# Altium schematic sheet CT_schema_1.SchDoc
size 493 x 314 mm
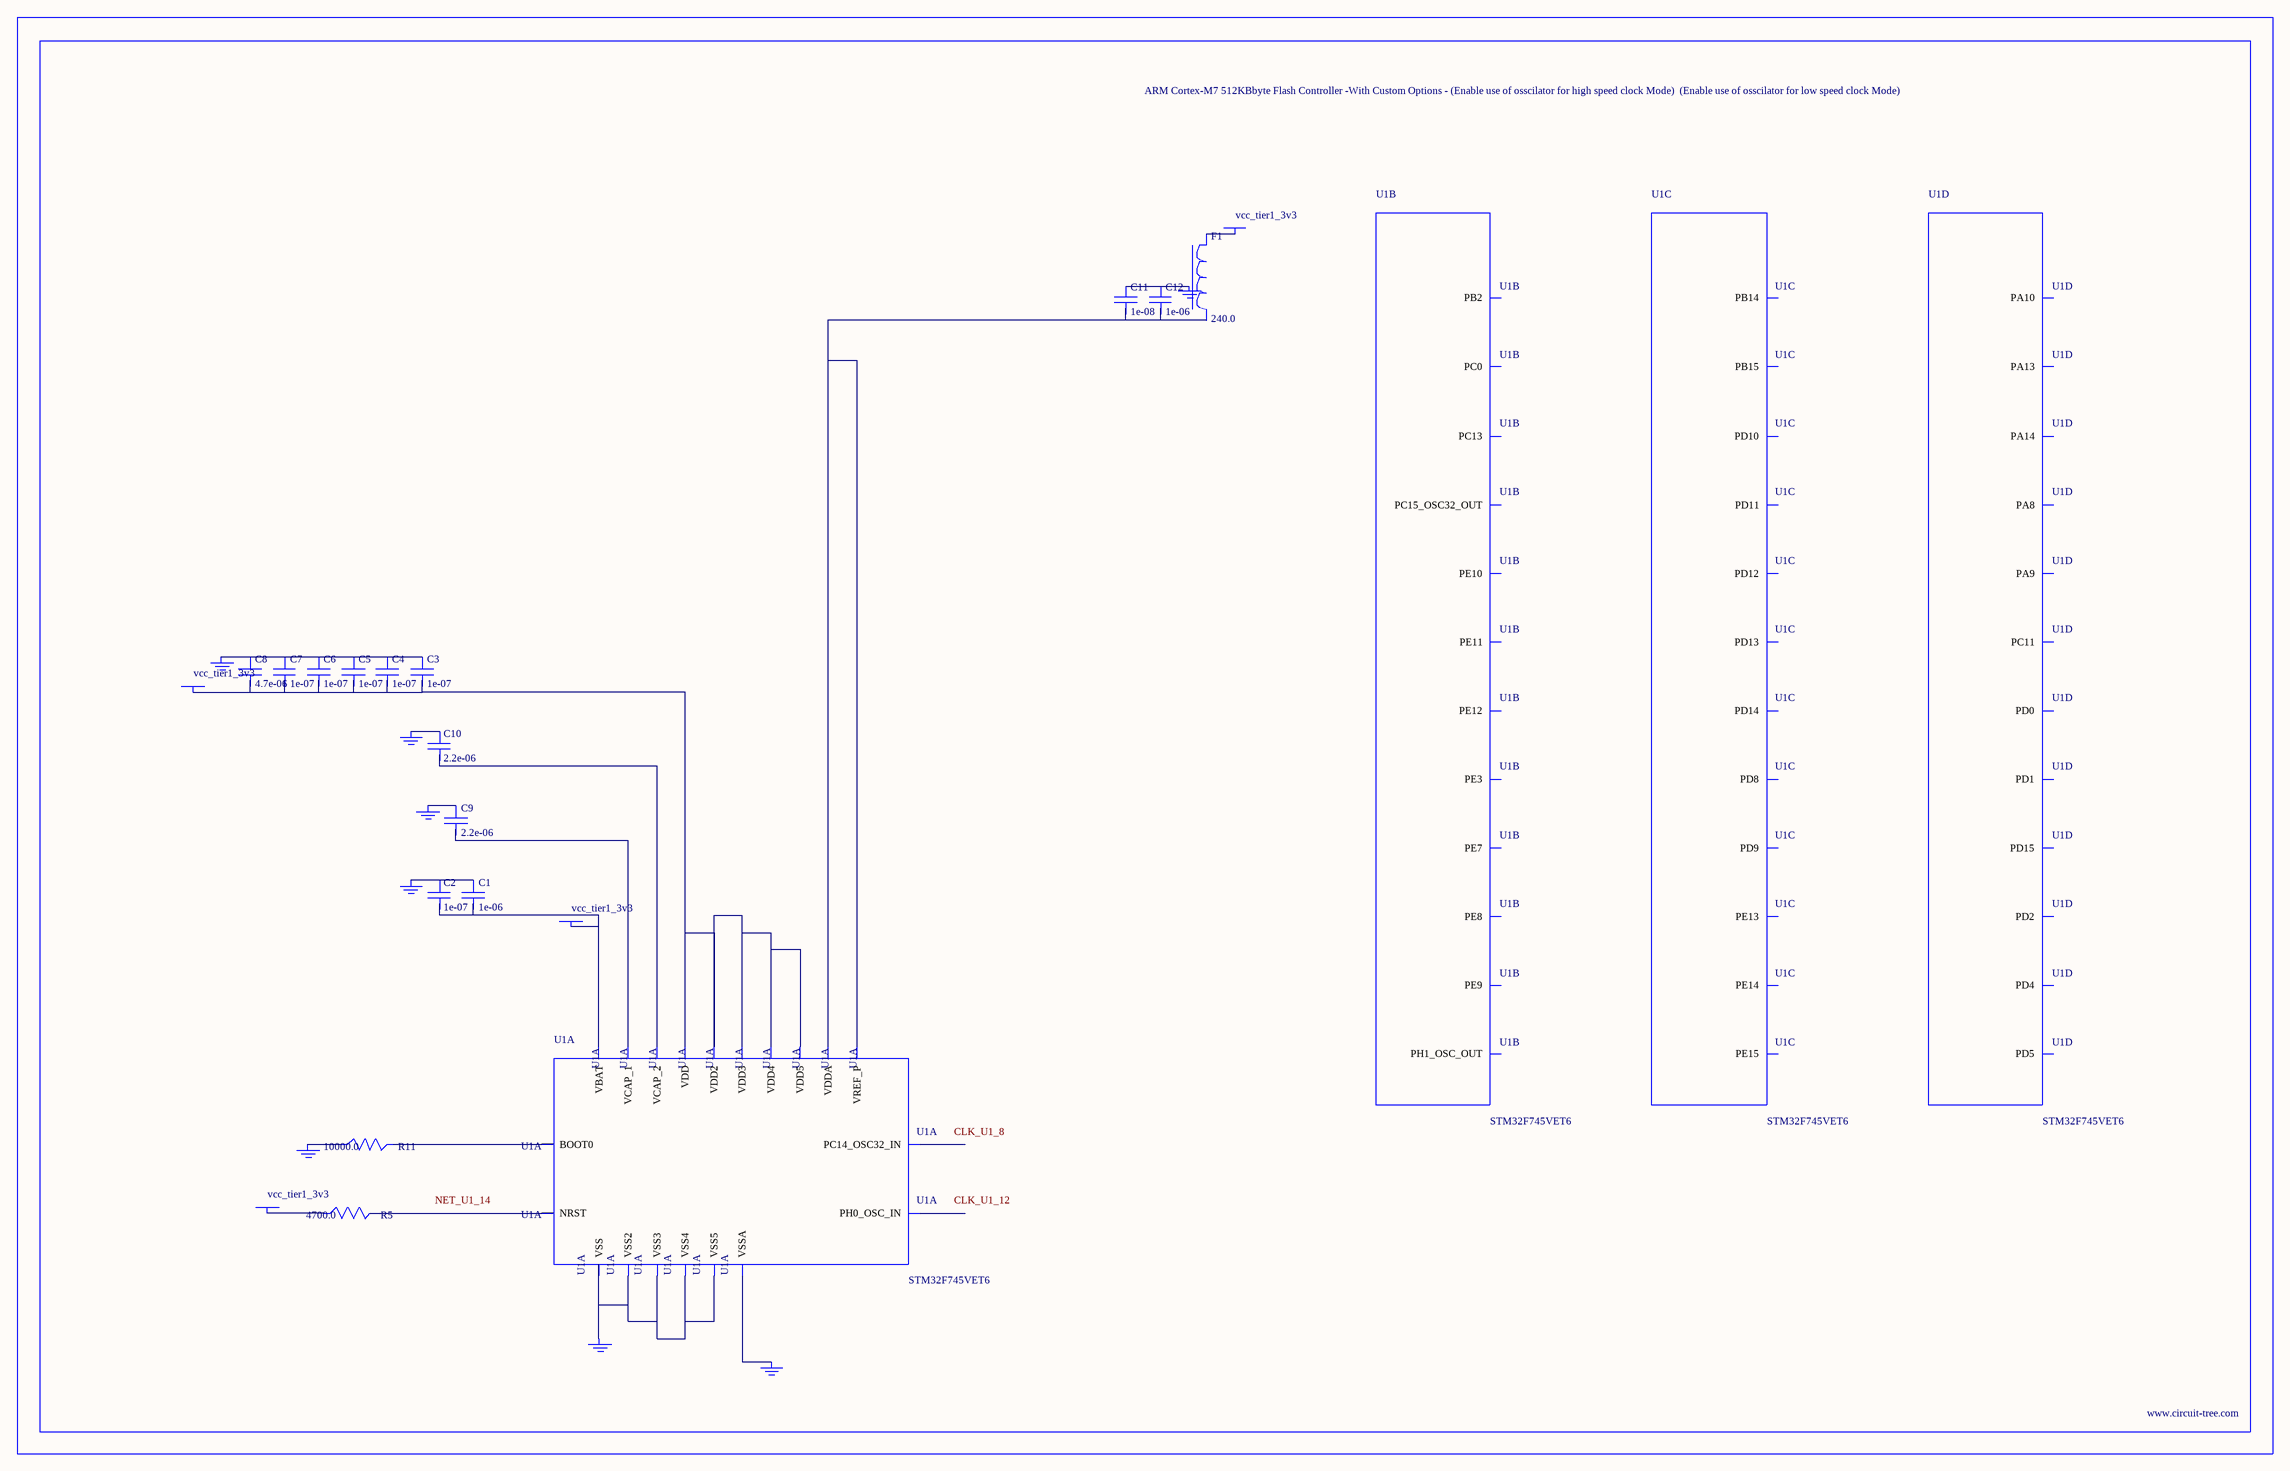
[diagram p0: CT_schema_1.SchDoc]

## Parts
BORDER0  (no value)
C1  1e-06  [C0603]
C2  1e-07  [C0603]
C3  1e-07  [C0603]
C4  1e-07  [C0603]
C5  1e-07  [C0603]
C6  1e-07  [C0603]
C7  1e-07  [C0603]
C8  4.7e-06  [C0603]
C9  2.2e-06  [C0603]
C10  2.2e-06  [C0603]
C11  1e-08  [C0603]
C12  1e-06  [C0603]
F1  240.0  [L0603]
GND_INSTANCE_0_0  (no value)
GND_INSTANCE_0_1  (no value)
GND_INSTANCE_0_2  (no value)
GND_INSTANCE_0_3  (no value)
GND_INSTANCE_0_4  (no value)
GND_INSTANCE_0_5  (no value)
GND_INSTANCE_0_6  (no value)
GND_INSTANCE_0_7  (no value)
POWER_INSTANCE_0_0  vcc_tier1_3v3
POWER_INSTANCE_0_1  vcc_tier1_3v3
POWER_INSTANCE_0_2  vcc_tier1_3v3
POWER_INSTANCE_0_3  vcc_tier1_3v3
R5  4700.0  [R0603]
R11  10000.0  [R0603]
U1  STM32F745VET6  [LQFP100]  (parts A,B,C,D of 9)

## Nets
NetC1_1: C1.1 C2.1 GND_INSTANCE_0_0.0(GND)
NetC1_2: C1.2 C2.2 POWER_INSTANCE_0_0.0(PWR) U1.6(VBAT)
NetC3_1: C3.1 C4.1 C5.1 C6.1 C7.1 C8.1 GND_INSTANCE_0_1.0(GND)
NetC3_2: C3.2 C4.2 C5.2 C6.2 C7.2 C8.2 POWER_INSTANCE_0_1.0(PWR) U1.11(VDD) U1.27(VDD2) U1.50(VDD3) U1.75(VDD4) U1.100(VDD5)
NetC9_1: C9.1 GND_INSTANCE_0_4.0(GND)
NetC9_2: C9.2 U1.48(VCAP_1)
NetC10_1: C10.1 GND_INSTANCE_0_5.0(GND)
NetC10_2: C10.2 U1.73(VCAP_2)
NetC11_1: C11.1 C12.1 GND_INSTANCE_0_3.0(GND)
NetC11_2: C11.2 C12.2 U1.20(VREF_P) U1.21(VDDA)
NetF1_1: F1.1 POWER_INSTANCE_0_2.0(PWR)
NetGND_INSTANCE_0_2_0: GND_INSTANCE_0_2.0(GND) U1.19(VSSA)
NetGND_INSTANCE_0_6_0: GND_INSTANCE_0_6.0(GND) R11.1
NetGND_INSTANCE_0_7_0: GND_INSTANCE_0_7.0(GND) U1.10(VSS) U1.26(VSS2) U1.49(VSS3) U1.74(VSS4) U1.99(VSS5)
NetPOWER_INSTANCE_0_3_0: POWER_INSTANCE_0_3.0(PWR) R5.1
NetR5_2: R5.2 U1.14(NRST)
NetR11_2: R11.2 U1.94(BOOT0)

Not connected (* = marked no-connect by the designer): F1 2; U1 2(PE3) 7(PC13) 8(PC14_OSC32_IN) 9(PC15_OSC32_OUT) 12(PH0_OSC_IN) 13(PH1_OSC_OUT) 15(PC0) 36(PB2) 37(PE7) 38(PE8) 39(PE9) 40(PE10) 41(PE11) 42(PE12) 43(PE13) 44(PE14) 45(PE15) 53(PB14) 54(PB15) 55(PD8) 56(PD9) 57(PD10) 58(PD11) 59(PD12) 60(PD13) 61(PD14) 62(PD15) 67(PA8) 68(PA9) 69(PA10) 72(PA13) 76(PA14) 79(PC11) 81(PD0) 82(PD1) 83(PD2) 85(PD4) 86(PD5)

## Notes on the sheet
- Labels drawn without touching a wire or pin: CLK_U1_8, CLK_U1_12, NET_U1_14

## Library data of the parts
BORDER0 = BORDER_PAGE0
C1 C12 = C0603C105K3RACTU
C2-C7 = 06035C104K4Z2A
C8 = GRM188R6YA475KE15D
C9 C10 = C0603C225K8RACTU
C11 = 06035C103K4Z2A
F1 = Z0603C241ASMST
GND_INSTANCE_0_0-GND_INSTANCE_0_7 = GND
POWER_INSTANCE_0_0-POWER_INSTANCE_0_3 = PWR
R5 = RC0603JR-074K7L
R11 = RC0603JR-0710KL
